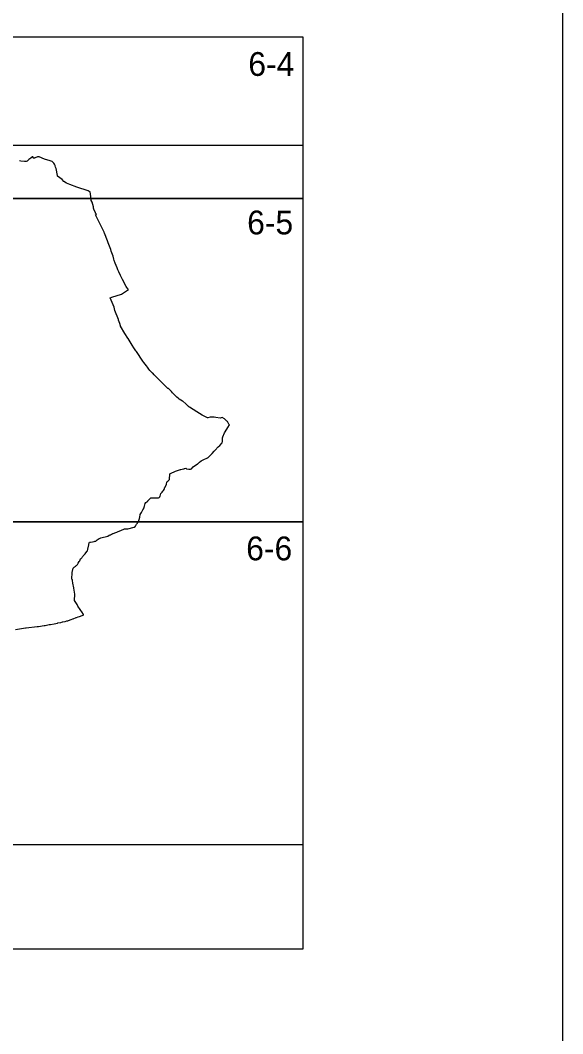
# Model space of a CAD drawing. Extents: x -449577 to -425530, y -1150048 to -1121091.
# Drawn here: x -431465.8 to -431256.1, y -1126663.9 to -1126271.9 of the extents above; entities that cross this region are included whole.
import ezdxf

# ---------------------------------------------------------------- set-up
doc = ezdxf.new("R2010")
doc.units = 0
for name, color, linetype in [('Vrstva 1', 7, 'Continuous'), ('Vrstva 10', 7, 'Continuous'), ('Vrstva 4', 7, 'Continuous')]:
    doc.layers.add(name, color=color, linetype=linetype)

msp = doc.modelspace()

# ---------------------------------------------------------------- linework, layer by layer
at = {"layer": 'Vrstva 1'}
msp.add_lwpolyline([(-432741.1, -1126016.81), (-432741.1, -1127066.81), (-431256.1, -1127066.81), (-431256.1, -1126016.81)], close=True, dxfattribs=at)
msp.add_lwpolyline([(-431467.64, -1126507.56), (-431463.77, -1126506.99), (-431463.53, -1126506.96), (-431459.23, -1126506.44), (-431458.7, -1126506.38), (-431456.55, -1126506.02), (-431456.23, -1126505.97), (-431454.57, -1126505.7), (-431454.17, -1126505.63), (-431452.76, -1126505.34), (-431451.47, -1126505.07), (-431451.26, -1126505.03), (-431450.09, -1126504.8), (-431449.42, -1126504.67), (-431449.4, -1126504.67), (-431448.49, -1126504.46), (-431448.42, -1126504.44), (-431447.77, -1126504.28), (-431447.42, -1126504.17), (-431446.53, -1126503.88), (-431446.09, -1126503.73), (-431445.44, -1126503.49), (-431445.32, -1126503.45), (-431444.23, -1126502.96), (-431444.23, -1126502.96), (-431444.11, -1126502.92), (-431443.46, -1126502.69), (-431443.37, -1126502.66), (-431442.94, -1126502.5), (-431441.28, -1126501.92), (-431441.3, -1126501.87), (-431441.41, -1126501.7), (-431441.57, -1126501.47), (-431441.79, -1126501.15), (-431443.49, -1126498.51), (-431443.7, -1126498.16), (-431443.87, -1126497.89), (-431444.31, -1126497.18), (-431444.84, -1126496.33), (-431444.68, -1126493.97), (-431444.67, -1126493.88), (-431445.06, -1126491.58), (-431445.06, -1126491.56), (-431445.07, -1126491.54), (-431445.07, -1126491.54), (-431445.07, -1126491.51), (-431445.48, -1126489.68), (-431445.49, -1126489.49), (-431445.55, -1126488.69), (-431445.65, -1126488.41), (-431445.66, -1126488.39), (-431445.77, -1126488.17), (-431445.81, -1126488.09), (-431445.82, -1126487.71), (-431445.85, -1126487.01), (-431445.8, -1126486.52), (-431445.8, -1126486.5), (-431445.71, -1126485.64), (-431445.69, -1126485.53), (-431445.4, -1126483.89), (-431445.32, -1126483.81), (-431445.02, -1126483.47), (-431444.96, -1126483.4), (-431444.7, -1126483.28), (-431444.64, -1126483.22), (-431444.38, -1126483.02), (-431444.15, -1126482.84), (-431443.94, -1126482.68), (-431443.88, -1126482.64), (-431443.8, -1126482.51), (-431443.72, -1126482.39), (-431443.61, -1126482.22), (-431443.39, -1126481.89), (-431442.97, -1126481.24), (-431442.84, -1126480.99), (-431442.83, -1126480.98), (-431442.69, -1126480.69), (-431442.64, -1126480.6), (-431442.46, -1126480.27), (-431442.32, -1126480.12), (-431442.02, -1126479.81), (-431441.85, -1126479.63), (-431441.57, -1126479.28), (-431441.44, -1126479.11), (-431440.75, -1126478.26), (-431440.09, -1126477.45), (-431439.8, -1126477.09), (-431439.56, -1126475.92), (-431439.5, -1126475.69), (-431439.43, -1126475.41), (-431439.11, -1126474.1), (-431439.03, -1126473.82), (-431439.03, -1126473.79), (-431439.01, -1126473.74), (-431438.85, -1126473.73), (-431438.83, -1126473.73), (-431438.59, -1126473.73), (-431437.9, -1126473.71), (-431437.89, -1126473.71), (-431437.86, -1126473.71), (-431437.18, -1126473.53), (-431436.98, -1126473.47), (-431436.56, -1126473.36), (-431436.54, -1126473.35), (-431436.48, -1126473.29), (-431436.18, -1126473.01), (-431436.06, -1126472.93), (-431435.72, -1126472.67), (-431435.3, -1126472.35), (-431435.23, -1126472.33), (-431434.67, -1126472.17), (-431431.97, -1126471.41), (-431431.38, -1126471.14), (-431431.05, -1126470.98), (-431431, -1126470.96), (-431430.9, -1126470.91), (-431430.54, -1126470.73), (-431430.49, -1126470.71), (-431430.46, -1126470.69), (-431430.45, -1126470.69), (-431430.42, -1126470.67), (-431430.11, -1126470.52), (-431430.05, -1126470.48), (-431429.94, -1126470.43), (-431428.86, -1126470.1), (-431428.43, -1126469.92), (-431427.91, -1126469.7), (-431426.9, -1126469.29), (-431425.48, -1126468.66), (-431425.34, -1126468.65), (-431424.21, -1126468.6), (-431421.81, -1126468.04), (-431421.28, -1126467.64), (-431421.21, -1126467.52), (-431421.12, -1126467.34), (-431420.86, -1126466.83), (-431420.51, -1126466.4), (-431420.49, -1126466.37), (-431420.28, -1126466.08), (-431420.17, -1126465.92), (-431420.16, -1126465.91), (-431419.62, -1126464.13), (-431419.61, -1126464.1), (-431419.41, -1126463.15), (-431419.15, -1126462.69), (-431418.96, -1126462.36), (-431418.41, -1126461.24), (-431418.03, -1126460.73), (-431418, -1126460.6), (-431417.93, -1126460.3), (-431417.9, -1126460.16), (-431417.84, -1126459.91), (-431417.82, -1126459.81), (-431417.5, -1126458.8), (-431417.49, -1126458.79), (-431417.2, -1126458.51), (-431416.54, -1126457.88), (-431416.49, -1126457.83), (-431416.02, -1126457.35), (-431415.76, -1126457.09), (-431415.66, -1126456.98), (-431415.29, -1126456.66), (-431415.25, -1126456.66), (-431415.24, -1126456.66), (-431414.83, -1126456.65), (-431414.66, -1126456.66), (-431414.03, -1126456.68), (-431413.32, -1126456.68), (-431412.35, -1126456.59), (-431412.32, -1126456.59), (-431412.07, -1126456.56), (-431411.85, -1126456.2), (-431411.8, -1126456.07), (-431411.78, -1126456.02), (-431411.76, -1126455.96), (-431411.4, -1126454.94), (-431411.26, -1126454.77), (-431411.16, -1126454.66), (-431411.12, -1126454.62), (-431411.06, -1126454.54), (-431410.94, -1126454.41), (-431410.67, -1126454.09), (-431410.58, -1126453.99), (-431410.48, -1126453.87), (-431410.14, -1126453.48), (-431410.07, -1126453.09), (-431410.01, -1126452.78), (-431409.94, -1126452.65), (-431409.39, -1126451.73), (-431409.28, -1126451.34), (-431409.09, -1126450.64), (-431408.97, -1126450.35), (-431408.68, -1126450.08), (-431408.13, -1126449.57), (-431408.06, -1126449.51), (-431407.96, -1126447.4), (-431406.94, -1126446.91), (-431406.54, -1126446.7), (-431406.29, -1126446.57), (-431406, -1126446.41), (-431405.78, -1126446.33), (-431405.44, -1126446.2), (-431405.39, -1126446.19), (-431404.3, -1126445.78), (-431404.29, -1126445.78), (-431403.8, -1126445.72), (-431403.72, -1126445.7), (-431402.69, -1126445.44), (-431402.54, -1126445.4), (-431402.45, -1126445.37), (-431402.28, -1126445.32), (-431401.75, -1126445.15), (-431401.75, -1126445.15), (-431401.74, -1126445.16), (-431401.74, -1126445.16), (-431401.71, -1126445.22), (-431401.58, -1126445.44), (-431400.7, -1126445.54), (-431400.5, -1126445.56), (-431400.14, -1126445.6), (-431400.05, -1126445.56), (-431399.62, -1126445.38), (-431398.97, -1126444.67), (-431397.33, -1126443.51), (-431397.24, -1126443.44), (-431397.07, -1126443.33), (-431396.56, -1126442.91), (-431395.81, -1126442.31), (-431394.54, -1126441.74), (-431393.92, -1126441.47), (-431393.38, -1126441.23), (-431393.32, -1126441.2), (-431391.67, -1126439.53), (-431390.83, -1126438.64), (-431390.47, -1126438.26), (-431389.28, -1126436.9), (-431388.68, -1126436.44), (-431388.63, -1126436.4), (-431387.79, -1126435.39), (-431387.59, -1126434.82), (-431387.68, -1126433.49), (-431387.46, -1126433), (-431386.82, -1126431.55), (-431385.36, -1126429.07), (-431385.33, -1126429.02), (-431385.33, -1126429.02), (-431385.31, -1126428.99), (-431385.28, -1126428.95), (-431385.13, -1126428.76), (-431384.87, -1126428.42), (-431385.13, -1126428.12), (-431385.27, -1126427.9), (-431385.74, -1126427.16), (-431385.94, -1126426.97), (-431386.09, -1126426.81), (-431386.28, -1126426.61), (-431386.86, -1126426.04), (-431387.71, -1126425.57), (-431388.16, -1126425.75), (-431388.49, -1126425.87), (-431390.24, -1126425.6), (-431390.85, -1126425.51), (-431390.99, -1126425.5), (-431391.58, -1126425.48), (-431391.96, -1126425.43), (-431392.12, -1126425.4), (-431392.16, -1126425.4), (-431392.19, -1126425.39), (-431392.19, -1126425.39), (-431392.22, -1126425.4), (-431392.32, -1126425.43), (-431392.45, -1126425.46), (-431393.35, -1126425.7), (-431393.42, -1126425.67), (-431395.49, -1126424.63), (-431397.51, -1126423.35), (-431400.42, -1126421.53), (-431400.58, -1126421.39), (-431400.62, -1126421.36), (-431400.71, -1126421.28), (-431401.85, -1126420.35), (-431403, -1126419.3), (-431403.11, -1126419.2), (-431404.32, -1126418.44), (-431404.6, -1126418.21), (-431405.23, -1126417.71), (-431405.54, -1126417.47), (-431406.04, -1126416.94), (-431406.76, -1126416.18), (-431406.91, -1126416.02), (-431407.37, -1126415.53), (-431408.34, -1126414.5), (-431408.54, -1126414.39), (-431408.54, -1126414.39), (-431408.72, -1126414.3), (-431408.92, -1126414.2), (-431409.75, -1126413.37), (-431410.38, -1126412.74), (-431411.56, -1126411.57), (-431412.49, -1126410.63), (-431412.65, -1126410.48), (-431413.09, -1126410.03), (-431413.33, -1126409.79), (-431413.42, -1126409.7), (-431413.46, -1126409.66), (-431413.98, -1126409.14), (-431414.62, -1126408.49), (-431414.7, -1126408.41), (-431414.72, -1126408.39), (-431414.87, -1126408.24), (-431415.7, -1126407.4), (-431416.08, -1126406.9), (-431416.36, -1126406.53), (-431416.68, -1126406.1), (-431417.04, -1126405.62), (-431417.99, -1126404.36), (-431418.36, -1126403.82), (-431420.9, -1126400.08), (-431421.07, -1126399.82), (-431421.84, -1126398.63), (-431422.51, -1126397.62), (-431423.35, -1126396.29), (-431424.15, -1126395.02), (-431424.23, -1126394.89), (-431425.32, -1126393.04), (-431427, -1126390.19), (-431427, -1126390.18), (-431427, -1126390.18), (-431427.01, -1126390.18), (-431427.34, -1126389.2), (-431427.79, -1126387.9), (-431427.85, -1126387.7), (-431429.23, -1126384.19), (-431429.52, -1126382.94), (-431431, -1126379.26), (-431430.37, -1126379.06), (-431426.65, -1126377.82), (-431424.68, -1126376.6), (-431424.5, -1126376.49), (-431424.44, -1126376.45), (-431424.24, -1126376.33), (-431423.97, -1126376.16), (-431424.89, -1126374.97), (-431426.3, -1126372.19), (-431427.05, -1126370.72), (-431427.58, -1126369.56), (-431427.6, -1126369.52), (-431427.66, -1126369.39), (-431427.67, -1126369.36), (-431427.69, -1126369.33), (-431427.73, -1126369.24), (-431428.06, -1126368.51), (-431428.38, -1126367.72), (-431429.09, -1126365.95), (-431429.5, -1126364.91), (-431429.65, -1126364.28), (-431429.91, -1126363.15), (-431430.65, -1126361.26), (-431430.85, -1126360.66), (-431431.79, -1126358.03), (-431432.06, -1126357.31), (-431433.25, -1126354.22), (-431433.32, -1126354.04), (-431433.35, -1126353.96), (-431436.7, -1126347.15), (-431436.39, -1126347.01), (-431436.37, -1126347), (-431436.47, -1126346.83), (-431436.55, -1126346.73), (-431436.72, -1126346.5), (-431436.78, -1126346.42), (-431437.39, -1126344.94), (-431437.44, -1126344.65), (-431437.54, -1126344.19), (-431437.55, -1126344.13), (-431438.06, -1126342.29), (-431438.36, -1126341.66), (-431438.37, -1126341.58), (-431438.41, -1126341.22), (-431438.55, -1126340.13), (-431438.83, -1126338.29), (-431438.89, -1126338.27), (-431439.19, -1126338.17), (-431439.57, -1126337.91), (-431439.58, -1126337.91), (-431443.88, -1126336.5), (-431446.67, -1126335.52), (-431447.98, -1126334.9), (-431448.95, -1126334.34), (-431449.67, -1126333.56), (-431451.35, -1126332.29), (-431451.41, -1126331.99), (-431451.99, -1126329.29), (-431452.14, -1126328.75), (-431452.32, -1126328.24), (-431452.37, -1126328.08), (-431452.62, -1126327.56), (-431452.87, -1126327.25), (-431453.45, -1126326.56), (-431454.2, -1126326.35), (-431456.38, -1126325.69), (-431458.47, -1126324.73), (-431459.09, -1126324.73), (-431460.04, -1126325.1), (-431460.17, -1126325.19), (-431460.24, -1126325.24), (-431460.38, -1126325.34), (-431460.42, -1126325.37), (-431460.44, -1126325.35), (-431460.65, -1126325.1), (-431460.9, -1126324.82), (-431460.98, -1126324.72), (-431461.07, -1126324.76), (-431461.58, -1126325.15), (-431461.77, -1126325.3), (-431462.44, -1126325.82), (-431463.19, -1126326.38), (-431463.53, -1126326.6), (-431464.12, -1126326.56), (-431465.6, -1126326.41), (-431466.06, -1126326.32)], dxfattribs=at)
at = {"layer": 'Vrstva 10'}
msp.add_lwpolyline([(-431356.51, -1126320.23), (-431356.51, -1126631.21), (-431689.38, -1126631.21), (-431689.38, -1126465.91), (-431669.01, -1126465.91), (-431669.01, -1126340.91), (-431669.01, -1126320.23), (-431356.51, -1126320.23)], dxfattribs=at)
at = {"layer": 'Vrstva 4'}
msp.add_line((-431669.01, -1126278.41), (-431356.51, -1126278.41), dxfattribs=at)
msp.add_lwpolyline([(-431356.51, -1126278.41), (-431356.51, -1126340.91), (-431512.76, -1126340.91), (-431512.76, -1126278.41)], dxfattribs=at)
for points in [[(-431356.51, -1126340.91), (-431356.51, -1126465.91), (-431512.76, -1126465.91), (-431512.76, -1126340.91)], [(-431356.51, -1126465.91), (-431356.51, -1126590.91), (-431512.76, -1126590.91), (-431512.76, -1126465.91)]]:
    msp.add_lwpolyline(points, close=True, dxfattribs=at)

# ---------------------------------------------------------------- texts
at = {"layer": 'Vrstva 1'}
for s, p in [('6-4', (-431377.64, -1126293.46)), ('6-5', (-431378.09, -1126354.75)), ('6-6', (-431378.46, -1126480.82))]:
    msp.add_text(s, height=9.2, dxfattribs=at).set_placement(p)

doc.saveas('drawing.dxf')
